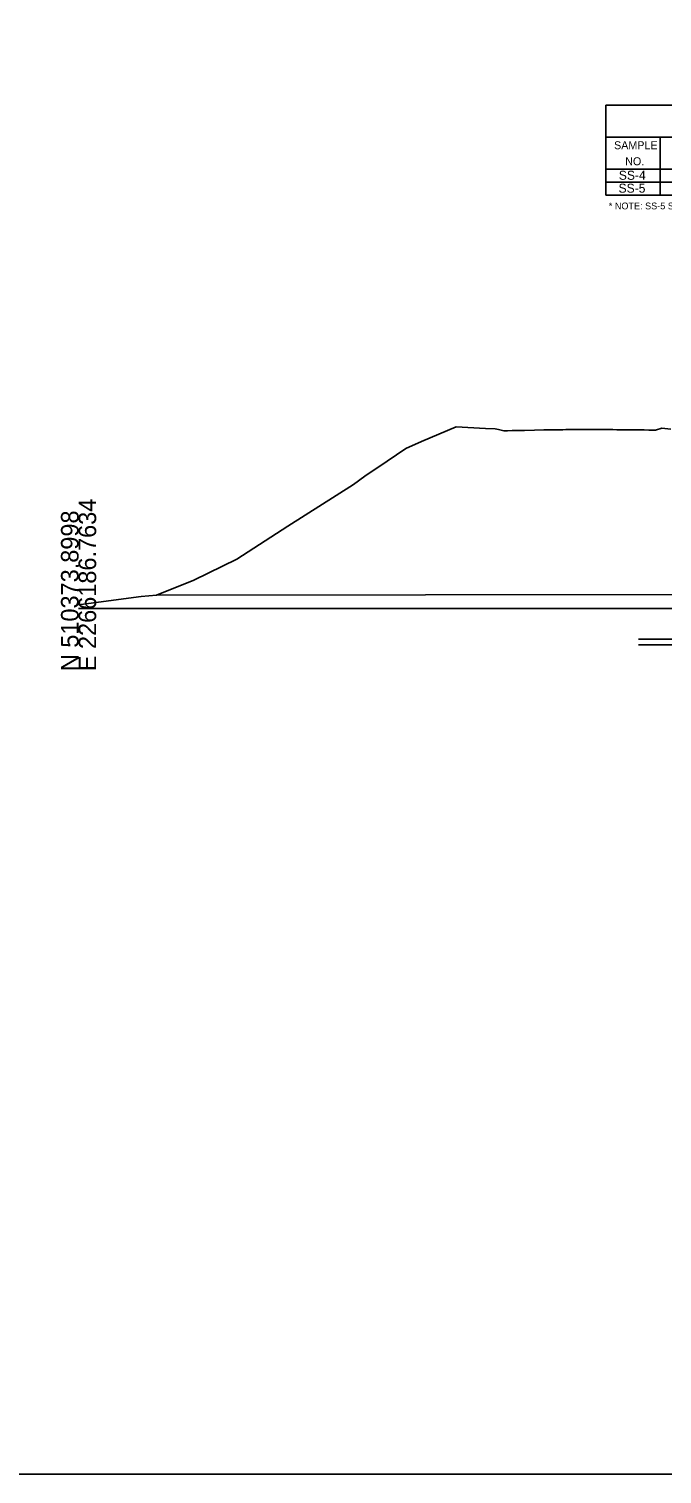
# Model space of a CAD drawing. Extents: x -827 to 2303, y -169 to 9934.
# Drawn here: x 992.1 to 1092.9, y -137.9 to 92.3 of the extents above; entities that cross this region are included whole.
import ezdxf

# ---------------------------------------------------------------- set-up
doc = ezdxf.new("R2010")
doc.units = 0
for name, color, linetype in [('Default', 7, 'Continuous'), ('Exist Cross Section Cell', 7, 'Continuous'), ('Exist XS Ground Line', 7, 'Continuous'), ('Geotech Sheets and Borders Cell', 7, 'Continuous'), ('Prop DirtTable_ Soil Test Results - Tx (Sample Data)', 7, 'Continuous'), ('Prop Road Sect_ Material - Contact (General - Major)', 7, 'Continuous'), ('Prop Road Sect_ Material - Contact (General - Minor)', 7, 'Continuous'), ('Scratch_Level_0', 7, 'Continuous')]:
    doc.layers.add(name, color=color, linetype=linetype)

msp = doc.modelspace()

# ---------------------------------------------------------------- linework, layer by layer
at = {"layer": 'Exist Cross Section Cell'}
msp.add_line((1000, 0), (1150, 0), dxfattribs=at)
at = {"layer": 'Exist XS Ground Line'}
msp.add_lwpolyline([(1000, 0.6), (1009.94, 1.91), (1012.4, 2.13), (1018.33, 4.48), (1025.17, 7.86), (1033.29, 13.13), (1043.78, 19.72), (1045.55, 21.05), (1049.14, 23.47), (1052.1, 25.46), (1054.59, 26.6), (1060.11, 28.93), (1064.77, 28.68), (1066.29, 28.61), (1066.81, 28.5), (1067.69, 28.31), (1068.27, 28.32), (1069.01, 28.33), (1070.02, 28.35), (1070.95, 28.37), (1072.56, 28.39), (1074.04, 28.44), (1075.07, 28.47), (1076.04, 28.47), (1076.65, 28.47), (1077.09, 28.48), (1077.57, 28.49), (1078.91, 28.52), (1079.51, 28.53), (1080.06, 28.53), (1081.57, 28.51), (1082.7, 28.49), (1084.13, 28.49), (1085.02, 28.49), (1085.68, 28.47), (1087.55, 28.44), (1089.24, 28.43), (1090.03, 28.43), (1090.75, 28.42), (1091.8, 28.4), (1092.84, 28.73), (1094.26, 28.57)], dxfattribs=at)
at = {"layer": 'Geotech Sheets and Borders Cell'}
for p, q in [((1083.9, 80.16), (1083.9, 69.96)), ((1083.9, 80.16), (1211.7, 80.16)), ((1083.9, 75.06), (1211.7, 75.06)), ((1092.58, 75.06), (1092.58, 67.9)), ((1083.9, 69.96), (1211.7, 69.96)), ((1083.9, 69.96), (1211.7, 69.96)), ((1083.9, 69.96), (1083.9, 67.9)), ((1083.9, 67.9), (1211.7, 67.9)), ((1083.9, 67.9), (1211.7, 67.9)), ((1083.9, 67.9), (1211.7, 67.9)), ((1083.9, 67.9), (1211.7, 67.9)), ((1083.9, 67.9), (1083.9, 65.84)), ((1092.58, 67.9), (1092.58, 65.84)), ((1083.9, 65.84), (1211.7, 65.84)), ((1083.9, 65.84), (1211.7, 65.84))]:
    msp.add_line(p, q, dxfattribs=at)
at = {"layer": 'Prop Road Sect_ Material - Contact (General - Major)'}
msp.add_line((1012.4, 2.13), (1232.52, 2.35), dxfattribs=at)
at = {"layer": 'Prop Road Sect_ Material - Contact (General - Minor)'}
for p, q in [((1267.35, -4.9), (1089.13, -4.9)), ((1267.61, -5.8), (1089.13, -5.8))]:
    msp.add_line(p, q, dxfattribs=at)
at = {"layer": 'Scratch_Level_0'}
msp.add_lwpolyline([(785.9, 1303.44), (1547.05, 1303.44), (1547.05, -137.9), (785.9, -137.9)], close=True, dxfattribs=at)

# ---------------------------------------------------------------- texts
at = {"layer": 'Default'}
msp.add_text('-', height=0.0001, dxfattribs=at).set_placement((1000, 0))
msp.add_text('-', height=0.0001, dxfattribs=at).set_placement((1000, 0))
at = {"layer": 'Exist Cross Section Cell'}
for s, p in [('E 2266186.7634', (1002.8, -10)), ('N 510373.8998', (1000, -10))]:
    msp.add_text(s, height=2.8, rotation=90, dxfattribs=at).set_placement(p)
at = {"layer": 'Geotech Sheets and Borders Cell'}
for s, p in [('SAMPLE', (1085.23, 73.15)), ('NO.', (1087, 70.6))]:
    msp.add_text(s, height=1.275, dxfattribs=at).set_placement(p)
at = {"layer": 'Prop DirtTable_ Soil Test Results - Tx (Sample Data)'}
for s, height, p in [('SS-4', 1.44, (1085.98, 68.29)), ('SS-5', 1.44, (1085.94, 66.23)), ('* NOTE: SS-5 STATION AND OFFSET REFERS TO -SR1- ALIGNMENT', 1.08, (1084.39, 63.58))]:
    msp.add_text(s, height=height, dxfattribs=at).set_placement(p)

doc.saveas('drawing.dxf')
